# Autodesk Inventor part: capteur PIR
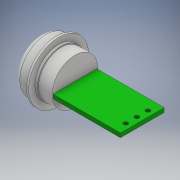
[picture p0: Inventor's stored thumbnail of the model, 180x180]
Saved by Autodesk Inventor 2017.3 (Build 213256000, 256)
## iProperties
Part Number: capteur PIR
Material: Générique
Document SubType Name: Modeling
Designer: ficho
Density: 1 g/cm^3
Appearance: Par défaut
Author: ficho
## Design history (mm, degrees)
sketch "Esquisse1"
  geometry: L1 (0.186, 0)-(0.186, 5.3); L2 (0.186, 5.3)-(-3.014, 5.3); L3 (-3.014, 5.55)-(-3.614, 5.55); L4 (-3.014, 5.3)-(-3.014, 5.55); L5 (-3.614, 7)-(-4.114, 7); L6 (-4.114, 7)-(-4.114, 6.15); L7 (-3.614, 5.55)-(-3.614, 7); L8 (-4.114, 6.15)-(-6.514, 6.15); L9 (-8.514, 3.234)-(-8.514, 0); L10 (0.186, 0)-(-8.514, 0); A1 r 3.126 centre (-5.389, 3.234) between (-6.514, 6.15) and (-8.514, 3.234); 1 further point
  constraints: 20 end point, 4 horizontal, 2 point on circle, 1 centre point, 1 parallel, 1 perpendicular, 1 tangent
  dimensions: "d5" = 3.2 distance between parallel lines of L4 L1; "d6" = 0.6 distance between parallel lines of L4 L7; "d7" = 0.5 distance between parallel lines of L7 L6; "d8" = 2 distance from line of L8.end L9; "d9" = 2.4 distance from line of L6 L8.end
revolve "Révolution1" sketch "Esquisse1" stored, may be unused: angle "d10" = 90 deg
sketch "Esquisse2"
  geometry: L1 (0, 5.1)-(1, 5.1); L2 (1, 5.1)-(1, -5.1); L3 (1, -5.1)-(0, -5.1); L4 (0, -5.1)-(0, 5.1); 1 further point
  constraints: 8 end point, 2 parallel, 1 horizontal, 1 perpendicular
  dimensions: "d11" = 1 distance between parallel lines of L2 L4; "d12" = 10.2 distance between parallel lines of L3 L1; "d13" = 5.1 distance from line of L1 point (0, 0) (= 0.5 x d12)
extrude "Extrusion1" join sketch "Esquisse2" distance "d14" = 15.7; taper "d15" = 0 deg
sketch "Esquisse3"
  geometry: L1 (0, 10.2)-(15.7, 10.2) reference; L2 (0, 0)-(15.7, 0) reference; L3 (15.7, 10.2)-(15.7, 0) reference; C1 r 0.5 at (14.405, 7.68); C2 r 0.5 at (14.405, 5.1); C3 r 0.5 at (14.405, 2.52); 1 further point
  constraints: 3 centre point
  dimensions: "d16" = 2.58 distance of C2.centre C1.centre; "d17" = 2.58 distance of C3.centre C2.centre (= d16); "d18" = 2.52 distance from line of C1.centre L1 (computed from d16); "d20" = 1 diameter of C1 (= d22); "d21" = 1 diameter of C2; "d22" = 1 diameter of C3 (= d21); "d23" = 10.2 distance between parallel lines of L2 L1 (derived); "d26" = 1.295 distance from line of C3.centre L3; "d27" = 1.295 distance from line of L3 C2.centre (= d26); "d28" = 1.295 distance from line of L3 C1.centre (= d26)
extrude "Extrusion2" cut sketch "Esquisse3" stored distance "d24" = 15.7; taper "d25" = 0 deg
node "Solide1"
